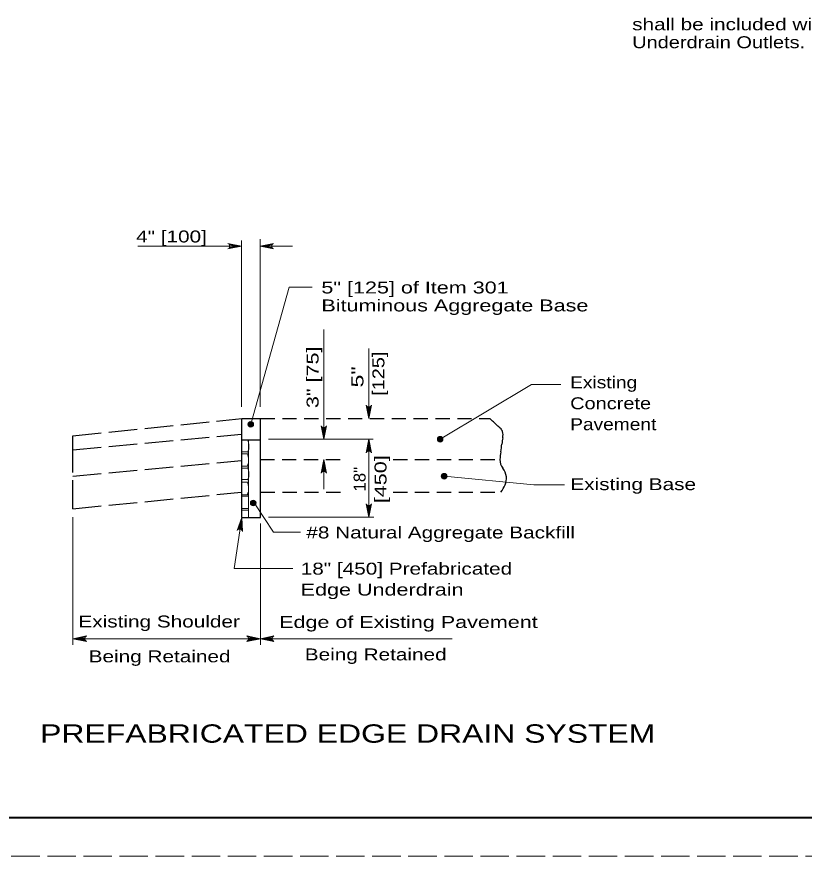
# Model space of a CAD drawing. Extents: x 743.9 to 777.9, y 1051 to 1073.
# Drawn here: x 757.15 to 767.45, y 1051.02 to 1062 of the extents above; entities that cross this region are included whole.
import ezdxf
from ezdxf.enums import TextEntityAlignment as Align

# ---------------------------------------------------------------- set-up
doc = ezdxf.new("R2010")
doc.units = 0
doc.header["$LTSCALE"] = 0.062
doc.linetypes.add('LONG_DASHED', pattern=[7.5, 6, -1.5])
doc.linetypes.add('MEDIUM_DASHED', pattern=[4.5, 3, -1.5])
doc.layers.add('1', color=7, linetype='Continuous', lineweight=13)

msp = doc.modelspace()

# ---------------------------------------------------------------- hatches: boundary and pattern name
at = {"layer": '1'}
for points in [[(760.24751, 1056.66613, 1), (760.17435, 1056.66613, 1)], [(762.72374, 1056.47137, 1), (762.65059, 1056.47137, 1)], [(762.77544, 1055.98705, 1), (762.70229, 1055.98705, 1)], [(760.27957, 1055.63724, 1), (760.20642, 1055.63724, 1)], [(760.26508, 1055.63724, 1), (760.24299, 1055.63724, 1)]]:
    msp.add_hatch(color=256, dxfattribs=at).paths.add_polyline_path(points)

# ---------------------------------------------------------------- linework, layer by layer
for p, q in [((758.73333, 1058.99475), (760.0895, 1058.99475)), ((759.92742, 1058.96992), (760.0895, 1058.99475)), ((759.92925, 1059.01717), (760.0895, 1058.99475)), ((759.9335, 1058.98033), (760.0895, 1058.99475)), ((759.93475, 1059.00608), (760.0895, 1058.99475)), ((759.93633, 1058.99475), (760.0895, 1058.99475)), ((760.0895, 1056.89608), (760.0895, 1059.07025)), ((760.3325, 1056.89608), (760.3325, 1059.08567)), ((760.493, 1059.01717), (760.33275, 1058.99475)), ((760.48758, 1059.00608), (760.33275, 1058.99475)), ((760.48592, 1058.99475), (760.33275, 1058.99475)), ((760.48875, 1058.98033), (760.33275, 1058.99475)), ((760.49492, 1058.96992), (760.33275, 1058.99475)), ((760.33275, 1058.99475), (760.75817, 1058.99475)), ((760.21092, 1056.66617), (760.71142, 1058.45892)), ((760.71142, 1058.45892), (761.01383, 1058.45892)), ((761.16667, 1056.47008), (761.16667, 1057.907)), ((761.75425, 1056.74017), (761.75425, 1057.657)), ((762.68717, 1056.47133), (763.8835, 1057.185)), ((763.8835, 1057.185), (764.2655, 1057.185)), ((761.72942, 1056.90233), (761.75425, 1056.74017)), ((761.73983, 1056.89617), (761.75425, 1056.74017)), ((761.77667, 1056.90042), (761.75425, 1056.74017)), ((761.76558, 1056.895), (761.75425, 1056.74017)), ((761.75425, 1056.89333), (761.75425, 1056.74017)), ((761.14425, 1056.63025), (761.16667, 1056.47008)), ((761.15533, 1056.62483), (761.16667, 1056.47008)), ((761.1915, 1056.63217), (761.16667, 1056.47008)), ((761.18108, 1056.626), (761.16667, 1056.47008)), ((761.16667, 1056.62325), (761.16667, 1056.47008)), ((760.44392, 1056.47258), (761.812, 1056.47258)), ((761.72942, 1056.30792), (761.75425, 1056.47008)), ((761.73983, 1056.31408), (761.75425, 1056.47008)), ((761.75425, 1056.31692), (761.75425, 1056.47008)), ((761.76558, 1056.31525), (761.75425, 1056.47008)), ((761.77667, 1056.30983), (761.75425, 1056.47008)), ((760.18267, 1056.30775), (760.09183, 1056.30775)), ((760.18267, 1056.279), (760.09183, 1056.279)), ((761.14192, 1056.042), (761.16667, 1056.20417)), ((761.15225, 1056.04817), (761.16667, 1056.20417)), ((761.16667, 1055.81792), (761.16667, 1056.20417)), ((761.16667, 1056.051), (761.16667, 1056.20417)), ((761.178, 1056.04933), (761.16667, 1056.20417)), ((761.18908, 1056.04392), (761.16667, 1056.20417)), ((760.18267, 1056.11992), (760.09183, 1056.11992)), ((760.18267, 1056.0945), (760.09183, 1056.0945)), ((760.18267, 1055.94483), (760.09183, 1055.94483)), ((762.73883, 1055.98708), (763.91108, 1055.87625)), ((760.18267, 1055.91008), (760.09183, 1055.91008)), ((763.91108, 1055.87625), (764.315, 1055.87625)), ((760.18267, 1055.74417), (760.09183, 1055.74417)), ((760.18267, 1055.72575), (760.09183, 1055.72575)), ((760.5085, 1055.25658), (760.254, 1055.63717)), ((761.73183, 1055.61033), (761.75425, 1055.45008)), ((761.74292, 1055.60483), (761.75425, 1055.45008)), ((761.779, 1055.61217), (761.75425, 1055.45008)), ((761.76858, 1055.60608), (761.75425, 1055.45008)), ((761.75425, 1055.60325), (761.75425, 1055.45008)), ((760.18267, 1055.56483), (760.09183, 1055.56483)), ((760.18267, 1055.54142), (760.09183, 1055.54142)), ((757.88592, 1053.78392), (757.88592, 1055.45308)), ((760.04733, 1055.29133), (760.09283, 1055.44658)), ((760.05917, 1055.29508), (760.09283, 1055.44658)), ((760.07058, 1055.29508), (760.09283, 1055.44658)), ((760.08442, 1055.29017), (760.09283, 1055.44658)), ((760.09375, 1055.28258), (760.09283, 1055.44658)), ((760.33617, 1053.78392), (760.33617, 1055.36867)), ((760.44392, 1055.45008), (761.82117, 1055.45008)), ((760.5085, 1055.25658), (760.8635, 1055.25658)), ((758.04617, 1053.885), (757.88592, 1053.86258)), ((758.04075, 1053.87392), (757.88592, 1053.86258)), ((757.88592, 1053.86258), (762.84633, 1053.86258)), ((758.03908, 1053.86258), (757.88592, 1053.86258)), ((758.04192, 1053.84817), (757.88592, 1053.86258)), ((758.04808, 1053.83775), (757.88592, 1053.86258)), ((760.174, 1053.83775), (760.33617, 1053.86258)), ((760.17592, 1053.885), (760.33617, 1053.86258)), ((760.18017, 1053.84817), (760.33617, 1053.86258)), ((760.18133, 1053.87392), (760.33617, 1053.86258)), ((760.183, 1053.86258), (760.33617, 1053.86258)), ((760.49642, 1053.885), (760.33617, 1053.86258)), ((760.49092, 1053.87392), (760.33617, 1053.86258)), ((760.48933, 1053.86258), (760.33617, 1053.86258)), ((760.49217, 1053.84817), (760.33617, 1053.86258)), ((760.49825, 1053.83775), (760.33617, 1053.86258))]:
    msp.add_line(p, q, dxfattribs=at)
at = {"layer": '1', "linetype": 'LONG_DASHED', "lineweight": 25}
for p, q in [((757.88667, 1056.51642), (760.09283, 1056.74017)), ((757.88667, 1056.33117), (760.08975, 1056.53842)), ((757.88667, 1056.33242), (757.88667, 1056.51642)), ((757.88667, 1055.56225), (757.88667, 1056.33083)), ((757.88667, 1055.98633), (760.08975, 1056.19342)), ((757.88667, 1055.56225), (760.08725, 1055.77817))]:
    msp.add_line(p, q, dxfattribs=at)
at = {"layer": '1', "lineweight": 25}
for p, q in [((760.09283, 1055.44658), (760.09283, 1056.74017)), ((760.09283, 1056.74017), (760.33858, 1056.74017)), ((760.33758, 1055.44658), (760.33758, 1056.74067)), ((760.09183, 1056.46325), (760.3305, 1056.46325)), ((760.09283, 1055.44658), (760.33758, 1055.44658))]:
    msp.add_line(p, q, dxfattribs=at)
at = {"layer": '1', "linetype": 'MEDIUM_DASHED', "lineweight": 25}
for p, q in [((760.33858, 1056.74017), (763.336, 1056.74017)), ((760.33483, 1056.20533), (761.42908, 1056.20533)), ((762.07242, 1056.20533), (763.46833, 1056.20533)), ((760.33983, 1055.77817), (761.42908, 1055.77817)), ((762.07242, 1055.77817), (763.48125, 1055.77817))]:
    msp.add_line(p, q, dxfattribs=at)
at = {"layer": '1', "linetype": 'LONG_DASHED'}
msp.add_lwpolyline([(743.86317, 1051.01808), (777.86317, 1051.01808), (777.86317, 1073.01808), (743.86317, 1073.01808)], close=True, dxfattribs=at)
at = {"layer": '1', "lineweight": 25}
msp.add_lwpolyline([(777.36317, 1051.51808), (745.86317, 1051.51808), (745.86317, 1072.51808)], dxfattribs=at)
at = {"layer": '1', "lineweight": 40}
msp.add_lwpolyline([(745.86317, 1072.51808), (777.36317, 1072.51808), (777.36317, 1051.51808), (745.86317, 1051.51808)], close=True, dxfattribs=at)
msp.add_lwpolyline([(745.86317, 1072.51808), (777.36317, 1072.51808), (777.36317, 1051.51808), (745.86317, 1051.51808)], close=True, dxfattribs=at)
at = {"layer": '1'}
for points in [[(759.9125, 1058.95933), (760.0895, 1058.99475), (759.9125, 1059.03008)], [(760.50975, 1058.95933), (760.33275, 1058.99475), (760.50975, 1059.03008)], [(761.71883, 1056.91717), (761.75425, 1056.74017), (761.78967, 1056.91717)], [(761.20208, 1056.64708), (761.16667, 1056.47008), (761.13125, 1056.64708)], [(760.18267, 1055.44917), (760.18267, 1056.46325), (760.09183, 1056.46325)], [(761.71883, 1056.29308), (761.75425, 1056.47008), (761.78967, 1056.29308)], [(761.75425, 1055.45008), (761.75425, 1055.86775), (761.75425, 1056.47008)], [(761.13125, 1056.02717), (761.16667, 1056.20417), (761.20208, 1056.02717)], [(761.78967, 1055.62708), (761.75425, 1055.45008), (761.71883, 1055.62708)], [(760.09283, 1055.44658), (759.99558, 1054.78092), (760.76142, 1054.78092)], [(760.10217, 1055.26633), (760.09283, 1055.44658), (760.03208, 1055.27658)], [(758.06292, 1053.82717), (757.88592, 1053.86258), (758.06292, 1053.89792)], [(760.15917, 1053.82717), (760.33617, 1053.86258), (760.15917, 1053.89792)], [(760.51317, 1053.82717), (760.33617, 1053.86258), (760.51317, 1053.89792)]]:
    msp.add_lwpolyline(points, dxfattribs=at)
for centre, radius in [((760.21093, 1056.66613), 0.03658), ((762.68716, 1056.47137), 0.03658), ((762.73887, 1055.98705), 0.03658), ((760.24299, 1055.63724), 0.03658), ((760.25404, 1055.63724), 0.01104), ((760.25403, 1055.6372), 0.01087)]:
    msp.add_circle(centre, radius, dxfattribs=at)
for centre, radius, start, end in [((759.89824, 1058.99476), 0.0382, 292.08605, 67.91218), ((760.52407, 1058.99476), 0.0382, 112.08782, 247.91395), ((761.75427, 1056.93148), 0.0382, 202.08605, 337.91218), ((761.16664, 1056.66134), 0.0382, 202.08782, 337.91395), ((759.99787, 1056.37821), 0.19002, 335.43792, 27.43686), ((759.99357, 1056.19888), 0.19002, 335.43792, 27.43686), ((761.75427, 1056.27875), 0.0382, 22.08782, 157.91395), ((759.99787, 1056.01525), 0.19002, 335.43792, 27.43686), ((761.16672, 1056.01286), 0.0382, 22.08782, 157.91395), ((759.99357, 1055.82744), 0.19002, 335.43792, 27.43686), ((761.75419, 1055.64135), 0.0382, 202.08782, 337.91395), ((760.06499, 1055.25734), 0.0382, 13.72742, 149.55355), ((758.07719, 1053.86259), 0.0382, 112.08782, 247.91395), ((760.14484, 1053.86259), 0.0382, 292.08605, 67.91218), ((760.52742, 1053.86259), 0.0382, 112.08782, 247.91395)]:
    msp.add_arc(centre, radius, start, end, dxfattribs=at)
at = {"layer": '1', "lineweight": 25}
for centre, radius, start, end in [((762.86892, 1056.15725), 0.74707, 46.31458, 51.29555), ((773.26564, 1067.0435), 14.30624, 226.31778, 226.57814), ((762.05313, 1055.06029), 2.10645, 47.59441, 49.10997), ((763.40188, 1056.53554), 0.10758, 19.35735, 48.14395), ((765.01957, 1056.21417), 1.53855, 169.65131, 172.75174), ((763.32431, 1056.52492), 0.18495, 349.29221, 14.49152), ((761.56828, 1056.59082), 1.93367, 351.55388, 354.5835), ((765.59955, 1055.99222), 2.14181, 171.554, 174.2894), ((763.66047, 1056.20658), 0.1921, 180.37097, 216.29597), ((763.2702, 1055.92409), 0.28969, 11.21635, 35.63421), ((763.33, 1055.96419), 0.22494, 336.46092, 4.14352), ((763.10727, 1056.0557), 0.46571, 323.42507, 337.08263)]:
    msp.add_arc(centre, radius, start, end, dxfattribs=at)

# ---------------------------------------------------------------- texts
at = {"layer": '1'}
for s, height, width, p in [('shall be included with the cost of the 6" [150] Conduit Type F for ', 0.156, 1.3, (765.1985, 1061.8195)), ('Underdrain Outlets.', 0.156, 1.25, (765.1985, 1061.58483)), ('4" [100]', 0.156, 1.3, (758.71183, 1059.04433)), ('5" [125] of Item 301', 0.156, 1.35, (761.13458, 1058.37725)), ('Bituminous Aggregate Base', 0.156, 1.35, (761.13458, 1058.14258)), ('Existing', 0.156, 1.2, (764.38733, 1057.13733)), ('Concrete', 0.156, 1.25, (764.38733, 1056.86333)), ('Pavement', 0.156, 1.2, (764.38733, 1056.58933)), ('Existing Base', 0.156, 1.3, (764.39008, 1055.80525)), ('#8 Natural Aggregate Backfill', 0.156, 1.3, (760.93792, 1055.17375)), ('18" [450] Prefabricated', 0.156, 1.3, (760.86417, 1054.70058)), ('Edge Underdrain', 0.156, 1.35, (760.86417, 1054.42658)), ('Existing Shoulder', 0.156, 1.3, (757.95808, 1054.0095)), ('Edge of Existing Pavement', 0.156, 1.35, (760.58217, 1054.00258)), ('Being Retained', 0.156, 1.3, (760.91758, 1053.57883)), ('Being Retained', 0.156, 1.3, (758.09175, 1053.55375)), ('PREFABRICATED EDGE DRAIN SYSTEM', 0.24, 1.3, (757.4575, 1052.50233))]:
    msp.add_text(s, height=height, dxfattribs=dict(at, width=width)).set_placement(p)
at = {"layer": '1', "width": 1.35}
msp.add_text('3" [75]', height=0.156, rotation=90, dxfattribs=at).set_placement((761.09767, 1056.8785))
at = {"layer": '1'}
for s, width, p in [('[125]', 1.25, (761.958, 1057.32783)), ('5" ', 1.45, (761.684, 1057.32779)), ('[450]', 1.35, (761.98583, 1055.94783)), ('18"', 1.05, (761.71183, 1055.94783))]:
    msp.add_text(s, height=0.156, rotation=90, dxfattribs=dict(at, width=width)).set_placement(p, align=Align.CENTER)

doc.saveas('drawing.dxf')
